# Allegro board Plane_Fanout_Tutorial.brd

Outline 100 x 50 mm; copper layers: TOP, POWERPLANE_1, BOTTOM. Coordinates in mm from the lower left corner of the outline.
Outline path: rectangle 0,0 100,50

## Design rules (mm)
constraint set DEFAULT: min track width 0.28
net group DPD: nets D+ D-

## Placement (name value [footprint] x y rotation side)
C1  100uF  [1210]  9 28 0 top
C2  10uF  [0402-CAP]  15 35 270 top
C3  10uF  [0402-CAP]  34 8 180 top
C4  0.1uF  [0402-CAP]  6 23 0 top
C5  0.1uF  [0402-CAP]  6 20 0 top
C6  0.1uF  [0402-CAP]  8 40 90 top
C7  0.1uF  [0402-CAP]  36 16 90 top
C8  0.1uF  [0402-CAP]  5 40 90 top
C9  10uF  [0402-CAP]  15 24 180 top
IC1  PIC32MX440F512H  [SQFP-S-10X10-64]  24 26 90 top
JP1  -  [XTEND-DIGI-MODEM]  69 25 0 top
JP2  PIC 32 PROG  [1X06_LOCK]  16 13 0 top
MAIN_PWR  LED  [LED_LNJ]  24 4 90 top
NOREF  -  [unnamed]  96 46 0 top
NOREF#2  -  [unnamed]  4 46 0 top
NOREF#3  -  [unnamed]  96 4 0 top
NOREF#4  -  [unnamed]  4 4 0 top
R1  150  [0402-RES]  20 4 90 top
R2  56k  [0402-RES]  34 11 180 top
U1  LT1965EMS8E-1P5TRPBF  [MSOP-EP08_3X3_ADI]  9 34 0 top
X1  USB-B  [USB-MICROB]  26 46 180 top
Y1  8MHz  [CRYSTAL-SMD]  16 41 270 top

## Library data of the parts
C1-C9 = CAP NP
IC1 = PIC32MX440F512H
JP1 = XTEND-DIGI-MODEM
JP2 = M06_LOCK
MAIN_PWR = LED: Tolerance: TOL
R1 R2 = RESISTOR
U1 = LT1965EMS8E-1P5TRPBF_0: User Part Number: PN; Tolerance: TOL
X1 = USB-MICROB
Y1 = CRYSTAL

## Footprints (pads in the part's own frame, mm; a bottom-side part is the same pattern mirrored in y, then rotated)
1X06_LOCK
  round 1.88 hole 1.016: 1(0,0) 2(2.54,-0.254) 3(5.08,0) 4(7.62,-0.254) 5(10.16,0) 6(12.7,-0.254)
0402-CAP
  rect 0.7x0.9 smd: 1(-0.65,0) 2(0.65,0)
0402-RES
  rect 0.7x0.9 smd: 1(-0.65,0) 2(0.65,0)
1210
  rect 1.2x2 smd: 1(-1.6,0) 2(1.6,0)
CRYSTAL-SMD
  rect 1.1x1.9 smd: 1(-1.15,1.85) 2(-1.15,-1.85) 3(1.15,-1.85) 4(1.15,1.85)
LED_LNJ
  rect 0.445x0.95 smd: 1(-0.652,0) 2(0.652,0)
MSOP-EP08_3X3_ADI
  rect 1.397x0.432 smd: 1(-2.197,0.975) 2(-2.197,0.325) 3(-2.197,-0.325) 4(-2.197,-0.975) 5(2.197,-0.975) 6(2.197,-0.325) 7(2.197,0.325) 8(2.197,0.975)
  rect 1.676x1.88 smd: EPAD(0,0)
SQFP-S-10X10-64
  rect 1.6x0.295 smd: 1(-5.6,3.75) 2(-5.6,3.25) 3(-5.6,2.75) 4(-5.6,2.25) 5(-5.6,1.75) 6(-5.6,1.25) 7(-5.6,0.75) 8(-5.6,0.25) 9(-5.6,-0.25) 10(-5.6,-0.75) 11(-5.6,-1.25) 12(-5.6,-1.75) 13(-5.6,-2.25) 14(-5.6,-2.75) 15(-5.6,-3.25) 16(-5.6,-3.75) 33(5.6,-3.75) 34(5.6,-3.25) 35(5.6,-2.75) 36(5.6,-2.25) 37(5.6,-1.75) 38(5.6,-1.25) 39(5.6,-0.75) 40(5.6,-0.25) 41(5.6,0.25) 42(5.6,0.75) 43(5.6,1.25) 44(5.6,1.75) 45(5.6,2.25) 46(5.6,2.75) 47(5.6,3.25) 48(5.6,3.75)
  rect 0.295x1.6 smd: 17(-3.75,-5.6) 18(-3.25,-5.6) 19(-2.75,-5.6) 20(-2.25,-5.6) 21(-1.75,-5.6) 22(-1.25,-5.6) 23(-0.75,-5.6) 24(-0.25,-5.6) 25(0.25,-5.6) 26(0.75,-5.6) 27(1.25,-5.6) 28(1.75,-5.6) 29(2.25,-5.6) 30(2.75,-5.6) 31(3.25,-5.6) 32(3.75,-5.6) 49(3.75,5.6) 50(3.25,5.6) 51(2.75,5.6) 52(2.25,5.6) 53(1.75,5.6) 54(1.25,5.6) 55(0.75,5.6) 56(0.25,5.6) 57(-0.25,5.6) 58(-0.75,5.6) 59(-1.25,5.6) 60(-1.75,5.6) 61(-2.25,5.6) 62(-2.75,5.6) 63(-3.25,5.6) 64(-3.75,5.6)
unnamed
  round 4.064 hole 3.81: (0,0)
USB-MICROB
  rect 0.35x1.4 smd: D+(0,2.65) D-(-0.65,2.65) GND(1.3,2.65) ID(0.65,2.65) VBUS(-1.3,2.65)
  rect 1.8x1.9 smd: MT1(-3.8,0) MT2(3.8,0)
  rect 2.1x1.6 smd: MT3(-3.1,2.55) MT4(3.1,2.55)
  rect 1.9x1.9 smd: P_1(-1.2,0) P_2(1.2,0)
XTEND-DIGI-MODEM
  round 0 hole 3.3 unplated: (-26.5,14.5) (-26.5,-14.5) (26.5,14.5) (26.5,-14.5)
  round 1.422 hole 0.7: 1(-27.5,9) 2(-25.5,9) 3(-27.5,7) 4(-25.5,7) 5(-27.5,5) 6(-25.5,5) 7(-27.5,3) 8(-25.5,3) 9(-27.5,1) 10(-25.5,1) 11(-27.5,-1) 12(-25.5,-1) 13(-27.5,-3) 14(-25.5,-3) 15(-27.5,-5) 16(-25.5,-5) 17(-27.5,-7) 18(-25.5,-7) 19(-27.5,-9) 20(-25.5,-9)

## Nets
3.3V: C1.1 C4.1 C5.1 C6.1 C7.1 C8.1 IC1.10 IC1.19 IC1.26 IC1.35 IC1.38 JP2.2 R1.1 R2.2 U1.1 U1.2 U1.3
GND: C1.2 C2.2 C3.2 C4.2 C5.2 C6.2 C7.2 C8.2 C9.2 IC1.9 IC1.20 IC1.25 IC1.41 JP1.1 JP2.3 MAIN_PWR.1(CATHODE) U1.4 U1.5 U1.EPAD X1.GND Y1.2 Y1.4(GND_4)
VBUS: C2.1 IC1.34 JP1.2(VCC) U1.6(SHDN) U1.7 U1.8 X1.VBUS
CTS: IC1.21 JP1.9
D+: IC1.37 X1.D+
D-: IC1.36 X1.D-
PROG0: IC1.17 JP2.5
PROG1: IC1.18 JP2.4
RESET: IC1.7(_MCLR) JP2.1
RTS: IC1.29 JP1.10
SHDN: IC1.59 JP1.7
URX: IC1.31 JP1.6
UTX: IC1.32 JP1.5
N02210: C3.1 JP1.11 R2.1
N02258: IC1.39 Y1.1
N02262: IC1.40 Y1.3
N02281: C9.1 IC1.56
N02349: MAIN_PWR.2 R1.2

Pads without a net: IC1 1 2 3 4 5 6 8 11 12 13 14 15 16 22 23 24 27 28 30 33 42 43 44 45 46 47 48 49 50 51 52 53 54 55 57 58 60 61 62 63 64; JP1 3 4 8 12 13 14 15 16 17 18 19 20; JP2 6; X1 ID MT1 MT2 MT3 MT4 P_1 P_2

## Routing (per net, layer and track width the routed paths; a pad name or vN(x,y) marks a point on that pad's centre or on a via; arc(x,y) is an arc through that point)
3.3V: length 4.5
  POWERPLANE_1 w0.381: JP2.2 19.66,12.75 ; JP2.2 18.54,13.86 ; JP2.2 17.42,12.75 ; JP2.2 18.54,11.63
GND: length 8
  BOTTOM w0.381: 41.5,33.11 JP1.1 ; JP1.1 42.39,34 ; JP1.1 41.5,34.89 ; JP1.1 40.61,34 ; 21.08,11.88 JP2.3 ; JP2.3 19.96,13 ; JP2.3 22.2,13 ; JP2.3 21.08,14.12

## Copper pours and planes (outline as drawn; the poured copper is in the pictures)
3.3V on POWERPLANE_1: 0.3,49.7 99.7,49.7 99.7,0.3 0.3,0.3
GND on BOTTOM: 0.3,49.7 99.7,49.7 99.7,0.3 0.3,0.3
